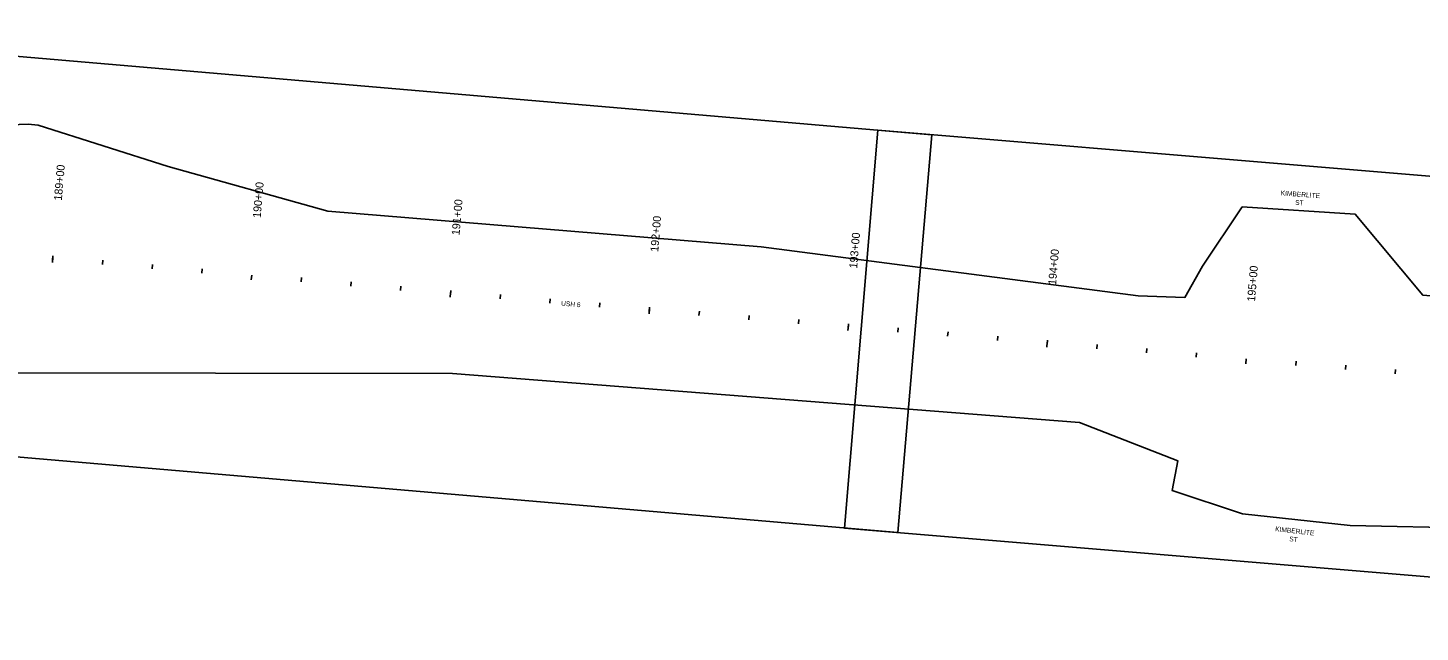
# Model space of a CAD drawing. Extents: x 20499876 to 20505320, y 7953544 to 7954108.
# Drawn here: x 20502593 to 20503290, y 7953634 to 7953937 of the extents above; entities that cross this region are included whole.
import ezdxf

# ---------------------------------------------------------------- set-up
doc = ezdxf.new("R2010")
doc.units = 0
for name, color, linetype in [('Alignment', 7, 'Continuous'), ('Curb', 7, 'Continuous'), ('Draft_0', 7, 'Continuous'), ('Draft_7', 7, 'Continuous'), ('UtilitiesBelowGround', 7, 'Continuous')]:
    doc.layers.add(name, color=color, linetype=linetype)

msp = doc.modelspace()

# ---------------------------------------------------------------- linework, layer by layer
at = {"layer": 'Alignment'}
for points in [[(20502421.05, 7953936.77), (20502403.97, 7953737.5), (20503028.68, 7953683.95), (20503045.76, 7953883.22)], [(20503018.63, 7953885.52), (20503002, 7953686.21), (20503626.83, 7953634.07), (20503643.46, 7953833.37)]]:
    msp.add_lwpolyline(points, close=True, dxfattribs=at)
at = {"layer": 'Curb'}
for p, q in [((20502605.28, 7953820.38), (20502605.47, 7953822.55)), ((20502705.01, 7953812.93), (20502704.8, 7953810.49)), ((20502804.53, 7953803.04), (20502804.72, 7953805.21)), ((20502904.18, 7953794.72), (20502904.37, 7953796.9)), ((20503003.84, 7953786.4), (20503004.02, 7953788.58)), ((20503103.49, 7953778.09), (20503103.67, 7953780.26)), ((20503203.25, 7953770.99), (20503203.04, 7953768.55))]:
    msp.add_line(p, q, dxfattribs=at)
at = {"layer": 'Draft_7'}
for p, q in [((20502605.39, 7953821.6), (20502605.18, 7953819.16)), ((20502630.19, 7953818.21), (20502630.38, 7953820.38)), ((20502655.1, 7953816.04), (20502655.28, 7953818.22)), ((20502680, 7953813.87), (20502680.19, 7953816.05)), ((20502705.01, 7953812.93), (20502704.8, 7953810.49)), ((20502729.81, 7953809.54), (20502730, 7953811.72)), ((20502754.72, 7953807.37), (20502754.91, 7953809.55)), ((20502779.62, 7953805.2), (20502779.81, 7953807.38)), ((20502804.64, 7953804.26), (20502804.42, 7953801.82)), ((20502829.44, 7953800.96), (20502829.63, 7953803.13)), ((20502854.36, 7953798.88), (20502854.54, 7953801.06)), ((20502879.27, 7953796.8), (20502879.45, 7953798.98)), ((20502904.29, 7953795.94), (20502904.08, 7953793.5)), ((20502929.1, 7953792.64), (20502929.28, 7953794.82)), ((20502954.01, 7953790.56), (20502954.19, 7953792.74)), ((20502978.92, 7953788.48), (20502979.11, 7953790.66)), ((20503003.94, 7953787.62), (20503003.74, 7953785.18)), ((20503028.75, 7953784.33), (20503028.93, 7953786.5)), ((20503053.66, 7953782.25), (20503053.85, 7953784.42)), ((20503078.58, 7953780.17), (20503078.76, 7953782.34)), ((20503103.59, 7953779.31), (20503103.39, 7953776.87)), ((20503128.4, 7953776.01), (20503128.59, 7953778.19)), ((20503153.32, 7953773.93), (20503153.5, 7953776.11)), ((20503178.23, 7953771.85), (20503178.41, 7953774.03)), ((20503203.25, 7953770.99), (20503203.04, 7953768.55)), ((20503228.06, 7953767.69), (20503228.24, 7953769.87)), ((20503252.97, 7953765.61), (20503253.15, 7953767.79)), ((20503277.89, 7953763.53), (20503278.07, 7953765.71))]:
    msp.add_line(p, q, dxfattribs=at)
at = {"layer": 'UtilitiesBelowGround'}
for points in [[(20502579.49, 7953887.98), (20502593.01, 7953888.5), (20502597.99, 7953888.06), (20502663.24, 7953867.31), (20502743.17, 7953845.01), (20502960.26, 7953827.03), (20503149.04, 7953802.5), (20503172.51, 7953801.74), (20503181.34, 7953817.32), (20503201.28, 7953847.18), (20503257.87, 7953843.36), (20503291.71, 7953802.91), (20503646.48, 7953772.26), (20503829.09, 7953744.97), (20504079.02, 7953722.08)], [(20503994.1, 7953676.75), (20503832.88, 7953690.55), (20503683.62, 7953704.36), (20503365.12, 7953730.13), (20503318.98, 7953693.96), (20503318.32, 7953686.11), (20503255.28, 7953687.43), (20503201.41, 7953693.27), (20503166.1, 7953705.05), (20503168.96, 7953719.94), (20503119.74, 7953739.09), (20502805.68, 7953763.59), (20502567.99, 7953764)]]:
    msp.add_lwpolyline(points, dxfattribs=at)

# ---------------------------------------------------------------- texts
at = {"layer": 'Curb'}
for s, rotation, p in [('190+00', 85.02642, (20502709.5, 7953841.42)), ('195+00', 85.22957, (20503207.64, 7953799.5))]:
    msp.add_text(s, height=4.008, rotation=rotation, dxfattribs=at).set_placement(p)
at = {"layer": 'Draft_0'}
for s, rotation, p in [('KIMBERLITE', 355.69975, (20503220.45, 7953852.91)), ('ST', 355.69975, (20503227.7, 7953848.15)), ('USH 6', 355, (20502859.94, 7953797.65)), ('KIMBERLITE', 353.48646, (20503217.65, 7953684.68)), ('ST', 353.48646, (20503224.71, 7953679.64))]:
    msp.add_text(s, height=2.4, rotation=rotation, dxfattribs=at).set_placement(p)
at = {"layer": 'Draft_7'}
for s, rotation, p in [('189+00', 85.02642, (20502609.88, 7953850.09)), ('190+00', 85.02642, (20502709.5, 7953841.42)), ('191+00', 85.02642, (20502809.13, 7953832.75)), ('192+00', 85.22957, (20502908.68, 7953824.45)), ('193+00', 85.22957, (20503008.33, 7953816.13)), ('194+00', 85.22957, (20503107.98, 7953807.82)), ('195+00', 85.22957, (20503207.64, 7953799.5))]:
    msp.add_text(s, height=4.008, rotation=rotation, dxfattribs=at).set_placement(p)

doc.saveas('drawing.dxf')
